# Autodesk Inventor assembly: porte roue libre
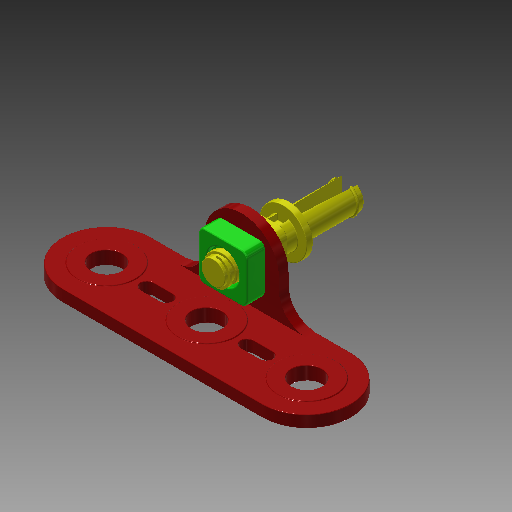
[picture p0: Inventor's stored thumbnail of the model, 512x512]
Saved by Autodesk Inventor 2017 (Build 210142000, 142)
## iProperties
Part Number: porte roue libre
Material: Générique
Document SubType Name: Assembly
Designer: ficho
Author: ficho
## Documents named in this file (4)
- G:\travail\année 2017-2018\1STI2D\challenge\porte roue libre.iam
- G:\travail\année 2017-2018\1STI2D\challenge\équerre meccano roue libre.ipt
- G:\travail\année 2017-2018\1STI2D\challenge\pièces meccano step\Nut.ipt
- G:\travail\année 2017-2018\1STI2D\challenge\pièces meccano step\A132.ipt
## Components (3 placed, 3 different names)
1. équerre meccano roue libre:1 — Logement:1, Logement:2
2. Nut:1 — Logement:2
3. A132:1 — Logement:1
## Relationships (2: Insert 2)
- Logement:1 [Insert]: équerre meccano roue libre:1 ↔ A132:1
- Logement:2 [Insert]: équerre meccano roue libre:1 ↔ Nut:1
